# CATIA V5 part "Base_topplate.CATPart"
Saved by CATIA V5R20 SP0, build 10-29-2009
Part number: Base_topplate
Source: Unknown
Bounding box of the stored display mesh (mm): x -55.271 to 394.729, y -195.133 to 254.867, z -54.55 to -42.55
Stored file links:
  C:\Users\Ikarus\OneDrive - FH JOANNEUM\BAC - Arbeit 1\CAD Modell\CAD-Modell-Step files\Base\Base_topplate.CATPart
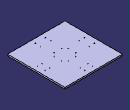
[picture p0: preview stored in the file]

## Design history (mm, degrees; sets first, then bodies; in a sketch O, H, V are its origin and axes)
Body1 (main body)
  Solid1 "Hauptkörper": solid without history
